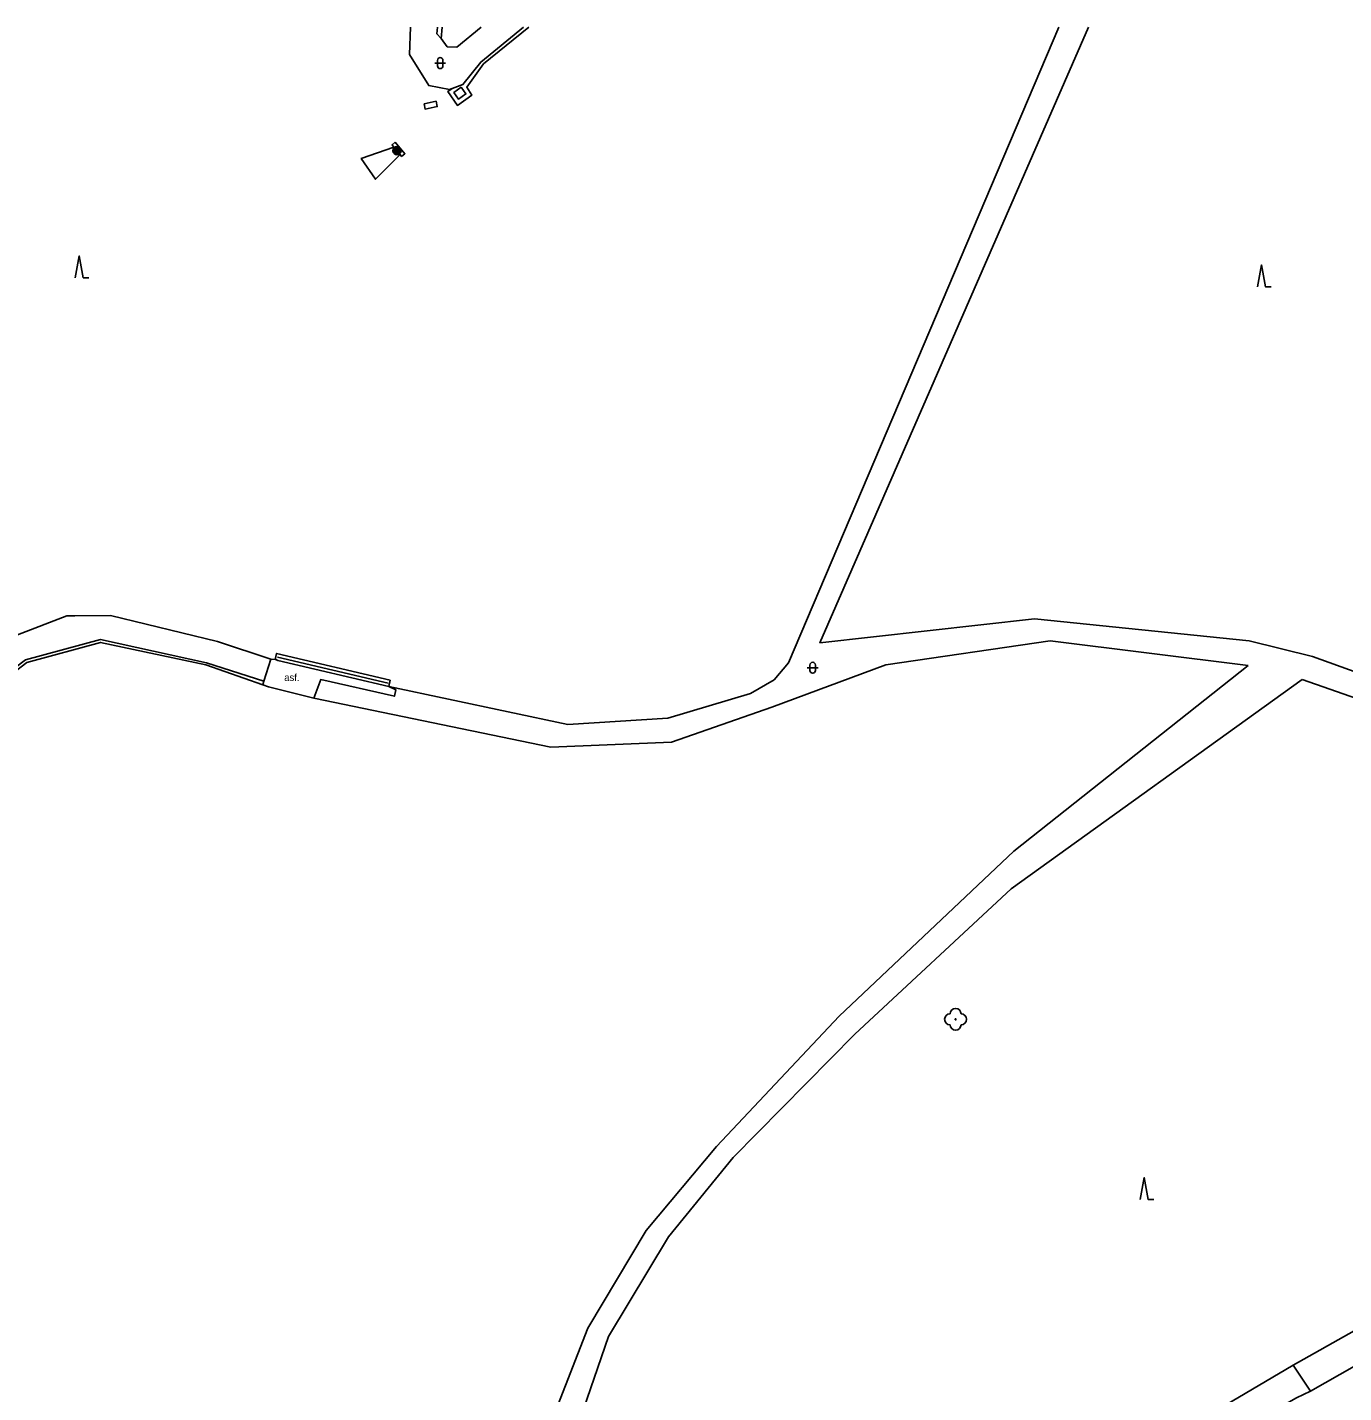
# Model space of a CAD drawing. Extents: x -600391 to -599491, y -1160176 to -1159402.
# Drawn here: x -600270.8 to -600150.5, y -1159526.6 to -1159401.8 of the extents above; entities that cross this region are included whole.
import ezdxf

# ---------------------------------------------------------------- set-up
doc = ezdxf.new("R2010")
doc.units = 0
for name, color, linetype in [('Level 10', 7, 'Continuous'), ('Level 11', 7, 'Continuous'), ('Level 14', 7, 'Continuous'), ('Level 22', 7, 'Continuous'), ('Level 31', 7, 'Continuous'), ('Level 36', 7, 'Continuous'), ('Level 40', 7, 'Continuous'), ('Level 9', 7, 'Continuous')]:
    doc.layers.add(name, color=color, linetype=linetype)

msp = doc.modelspace()

# ---------------------------------------------------------------- linework, layer by layer
at = {"layer": 'Level 10'}
for points in [[(-600120.27, -1159507.73), (-600136.33, -1159516.63), (-600153.54, -1159526.42)], [(-600153.54, -1159526.42), (-600154.83, -1159527.02), (-600172.64, -1159537.12), (-600185.69, -1159544.32), (-600201.38, -1159553.34), (-600222.37, -1159565.68), (-600245.39, -1159579.49), (-600266.13, -1159591.81)]]:
    msp.add_lwpolyline(points, dxfattribs=at)
at = {"layer": 'Level 11'}
msp.add_line((-600232.94, -1159402.79), (-600232.87, -1159401.77), dxfattribs=at)
for points in [[(-600237.74, -1159462.01), (-600221.38, -1159465.48), (-600212.25, -1159464.92), (-600204.69, -1159462.64), (-600202.52, -1159461.4), (-600201.21, -1159459.84), (-600176.54, -1159401.77)], [(-600235.76, -1159401.77), (-600235.83, -1159404.25), (-600234.09, -1159407.1), (-600232.18, -1159407.45), (-600231.96, -1159407.37)], [(-600233.28, -1159401.77), (-600233.35, -1159402.36), (-600232.94, -1159402.79)], [(-600232.94, -1159402.79), (-600232.39, -1159403.56), (-600231.53, -1159403.57), (-600229.31, -1159401.77)], [(-600231.96, -1159407.37), (-600232.33, -1159407.63), (-600231.46, -1159408.9), (-600230.14, -1159407.96), (-600230.62, -1159407.25), (-600229.08, -1159405.1), (-600224.94, -1159401.77)], [(-600231.96, -1159407.37), (-600230.97, -1159406.99), (-600229.34, -1159404.95), (-600225.44, -1159401.77)], [(-600173.82, -1159401.77), (-600198.35, -1159458.02), (-600178.76, -1159455.83), (-600159.15, -1159457.83), (-600153.36, -1159459.27), (-600140.92, -1159463.74), (-600127.94, -1159471.21), (-600124.01, -1159474.44), (-600121.85, -1159476.56), (-600116.94, -1159482.75)], [(-600231.11, -1159407.25), (-600230.69, -1159407.86), (-600231.36, -1159408.34), (-600231.78, -1159407.73), (-600231.11, -1159407.25)], [(-600234.49, -1159408.75), (-600233.41, -1159408.52), (-600233.31, -1159409.01), (-600234.42, -1159409.24), (-600234.49, -1159408.75)], [(-600237.26, -1159412.72), (-600240.25, -1159413.77), (-600238.96, -1159415.65), (-600236.71, -1159413.39)], [(-600237.26, -1159412.72), (-600237.44, -1159412.5), (-600237.15, -1159412.26)], [(-600236.71, -1159413.39), (-600237.26, -1159412.72)], [(-600237.15, -1159412.26), (-600236.27, -1159413.33), (-600236.56, -1159413.57), (-600236.71, -1159413.39)], [(-600248.5, -1159459.53), (-600253.38, -1159457.91), (-600263.16, -1159455.54), (-600266.42, -1159455.55), (-600267.14, -1159455.55), (-600271.65, -1159457.28), (-600279.87, -1159463.59), (-600284.81, -1159467.7), (-600286.03, -1159468.71), (-600297.54, -1159480.18), (-600299.34, -1159482.24), (-600301.09, -1159484.24), (-600309.25, -1159494.67), (-600314.1, -1159501.89), (-600316.53, -1159508.72), (-600319.29, -1159514.4), (-600322.78, -1159517.24), (-600325.68, -1159518.79)], [(-600366.85, -1159494.12), (-600365.92, -1159494.89), (-600364.91, -1159495.91), (-600356.86, -1159505.47), (-600345.22, -1159520.14), (-600341.74, -1159523.68), (-600339.55, -1159524.8), (-600333.59, -1159525.79), (-600332.13, -1159525.37), (-600327.27, -1159522.38), (-600321.66, -1159519.19), (-600317.54, -1159516.42), (-600316.09, -1159514.76), (-600315.11, -1159511.64), (-600313.54, -1159506.09), (-600309.91, -1159499.11), (-600306.73, -1159495.15), (-600296.37, -1159482.17), (-600284.77, -1159470.73), (-600278.6, -1159465.38), (-600270.93, -1159459.58), (-600264.06, -1159457.72), (-600254.39, -1159459.84), (-600249.14, -1159461.54)], [(-600249.24, -1159461.86), (-600254.44, -1159460.04), (-600264.07, -1159457.99), (-600270.8, -1159459.83), (-600278.39, -1159465.61), (-600284.51, -1159470.91), (-600296.11, -1159482.37), (-600308.68, -1159498.12), (-600313.26, -1159506.27), (-600315.98, -1159515.01), (-600316.88, -1159516.33)], [(-600244.57, -1159463.09), (-600222.94, -1159467.55), (-600211.92, -1159467.09), (-600202.74, -1159463.89), (-600192.34, -1159460.02), (-600177.33, -1159457.84), (-600159.23, -1159460.1)], [(-600248.5, -1159459.53), (-600249.14, -1159461.54)], [(-600248.12, -1159459.55), (-600248.5, -1159459.53)], [(-600248.12, -1159459.55), (-600247.99, -1159458.99), (-600237.61, -1159461.45), (-600237.74, -1159462.01)], [(-600237.74, -1159462.01), (-600247.87, -1159459.63), (-600248.06, -1159459.56), (-600248.12, -1159459.55)], [(-600227.24, -1159542.24), (-600224.54, -1159533.47), (-600219.56, -1159520.65), (-600214.22, -1159511.74), (-600207.81, -1159504.07), (-600196.59, -1159492.15), (-600180.64, -1159477.07), (-600159.23, -1159460.1)], [(-600249.14, -1159461.54), (-600249.24, -1159461.86)], [(-600249.24, -1159461.86), (-600248.71, -1159462.04), (-600244.57, -1159463.09)], [(-600244.57, -1159463.09), (-600243.95, -1159461.38), (-600237.22, -1159462.91), (-600237.08, -1159462.32), (-600237.74, -1159462.01)], [(-600224.72, -1159542.41), (-600221.94, -1159533.82), (-600217.67, -1159521.43), (-600212.17, -1159512.3), (-600206.29, -1159505.06), (-600195.16, -1159493.79), (-600180.89, -1159480.5), (-600154.3, -1159461.38)], [(-600119.38, -1159483.93), (-600124.15, -1159478.68), (-600129.2, -1159473.68), (-600142.96, -1159465.32), (-600154.3, -1159461.38)], [(-600155.12, -1159524.03), (-600137.91, -1159514.34), (-600124.74, -1159507.52), (-600118.08, -1159503.96), (-600116.96, -1159506.33)], [(-600153.54, -1159526.42), (-600155.12, -1159524.03)]]:
    msp.add_lwpolyline(points, dxfattribs=at)
at = {"layer": 'Level 14'}
msp.add_lwpolyline([(-600266.97, -1159590.29), (-600266.07, -1159589.95), (-600259.87, -1159586.44), (-600246.15, -1159578.35), (-600233.21, -1159570.29), (-600220.3, -1159561.9), (-600208.59, -1159555.32), (-600188.18, -1159543.56), (-600155.12, -1159524.03)], dxfattribs=at)
at = {"layer": 'Level 22'}
msp.add_circle((-600185.96, -1159492.43), 0.05, dxfattribs=at)
for centre, start, end in [((-600186.46, -1159492.43), 90, 270), ((-600185.96, -1159491.93), 0, 180), ((-600185.46, -1159492.43), 270, 90), ((-600185.96, -1159492.93), 180, 0)]:
    msp.add_arc(centre, 0.5, start, end, dxfattribs=at)
at = {"layer": 'Level 31'}
for radius in [0.375, 0.305, 0.235, 0.165, 0.0781]:
    msp.add_circle((-600236.99, -1159413.05), radius, dxfattribs=at)
at = {"layer": 'Level 36'}
for p, q in [((-600233.54, -1159405.04), (-600232.54, -1159405.04)), ((-600233.29, -1159404.79), (-600233.29, -1159405.29)), ((-600232.79, -1159404.79), (-600232.79, -1159405.29)), ((-600199.51, -1159460.3), (-600198.51, -1159460.3)), ((-600199.26, -1159460.05), (-600199.26, -1159460.55)), ((-600198.76, -1159460.05), (-600198.76, -1159460.55))]:
    msp.add_line(p, q, dxfattribs=at)
for points in [[(-600266.4, -1159424.66), (-600266.02, -1159422.66), (-600265.65, -1159424.66), (-600265.15, -1159424.66)], [(-600158.39, -1159425.49), (-600158.01, -1159423.49), (-600157.64, -1159425.49), (-600157.14, -1159425.49)], [(-600169.11, -1159508.9), (-600168.73, -1159506.9), (-600168.36, -1159508.9), (-600167.86, -1159508.9)]]:
    msp.add_lwpolyline(points, dxfattribs=at)
for centre, start, end in [((-600233.04, -1159404.79), 0, 180), ((-600233.04, -1159405.29), 180, 0), ((-600199.01, -1159460.05), 0, 180), ((-600199.01, -1159460.55), 180, 0)]:
    msp.add_arc(centre, 0.25, start, end, dxfattribs=at)
at = {"layer": 'Level 9'}
msp.add_lwpolyline([(-600247.9, -1159459.32), (-600237.8, -1159461.72)], dxfattribs=at)

# ---------------------------------------------------------------- texts
at = {"layer": 'Level 40'}
msp.add_text('asf.', height=0.65, dxfattribs=at).set_placement((-600247.29, -1159461.51))

doc.saveas('drawing.dxf')
